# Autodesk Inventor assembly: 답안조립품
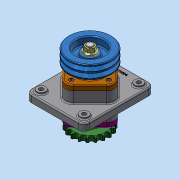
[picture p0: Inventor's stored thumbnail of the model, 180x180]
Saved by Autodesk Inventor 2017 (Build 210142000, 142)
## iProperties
Part Number: 답안조립품
Material: 일반
Document SubType Name: Assembly
Designer: MRC
Author: MRC
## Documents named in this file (16)
- C:\Users\MRC\Desktop\710707V1024\답안조립품.iam
- C:\Users\MRC\Desktop\710707V1024\본체.ipt
- C:\Users\MRC\Desktop\710707V1024\M16 너트.ipt
- C:\Users\MRC\Desktop\710707V1024\V-벨트풀리.ipt
- C:\Users\MRC\Desktop\710707V1024\멈춤나사 M4.ipt
- C:\Users\MRC\Desktop\710707V1024\베어링 6206.ipt
- C:\Users\MRC\Desktop\710707V1024\볼트 M6.ipt
- C:\Users\MRC\Desktop\710707V1024\부시.ipt
- C:\Users\MRC\Desktop\710707V1024\오일실 30x42x8.ipt
- C:\Users\MRC\Desktop\710707V1024\오일실 30x45x8.ipt
- C:\Users\MRC\Desktop\710707V1024\체인 스프로킷.ipt
- C:\Users\MRC\Desktop\710707V1024\축.ipt
- C:\Users\MRC\Desktop\710707V1024\커버A.ipt
- C:\Users\MRC\Desktop\710707V1024\커버B.ipt
- C:\Users\MRC\Desktop\710707V1024\키 6x6x18.ipt
- C:\Users\MRC\Desktop\710707V1024\키 6x6x20.ipt
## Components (3 placed, 2 different names)
1. M16 너트:1
2. V-벨트풀리:1
3. M16 너트:2
